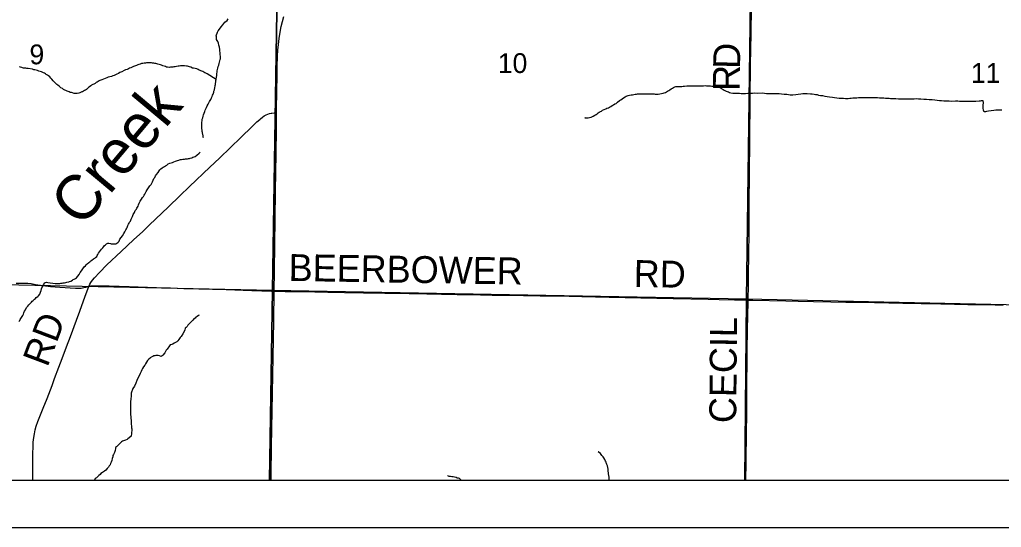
# Model space of a CAD drawing. Extents: x 0 to 34, y 0 to 22.
# Drawn here: x 3.072 to 5.144, y 14 to 15.073 of the extents above; entities that cross this region are included whole.
import ezdxf

# ---------------------------------------------------------------- set-up
doc = ezdxf.new("R2010")
doc.units = 0
for name, color, linetype in [('GM_X_County_Text', 7, 'Continuous'), ('GM_X_Minor_River', 7, 'Continuous'), ('GM_X_Minor_River_Text', 7, 'Continuous'), ('GM_X_Rail_Line_Text', 7, 'Continuous'), ('GM_X_Section', 7, 'Continuous'), ('GM_X_Section_Text', 7, 'Continuous'), ('GM_X_State_Route', 7, 'Continuous'), ('GM_X_Township_Road', 7, 'Continuous'), ('GM_X_Township_Road_Text', 7, 'Continuous'), ('SH_Cut_Line', 7, 'Continuous'), ('SH_Data', 7, 'Continuous')]:
    doc.layers.add(name, color=color, linetype=linetype)

msp = doc.modelspace()

# ---------------------------------------------------------------- linework, layer by layer
at = {"layer": 'GM_X_County_Text'}
msp.add_lwpolyline([(2.1, 14.1), (6.615, 14.1)], dxfattribs=at)
at = {"layer": 'GM_X_Minor_River'}
for points in [[(3.4599, 14.8236), (3.4596, 14.824), (3.4592, 14.8274), (3.4585, 14.8305), (3.4581, 14.8324), (3.4578, 14.8343), (3.4574, 14.8366), (3.457, 14.8396), (3.4567, 14.843), (3.4564, 14.8469), (3.4564, 14.8499), (3.4564, 14.8526), (3.4568, 14.856), (3.4572, 14.859), (3.4576, 14.8624), (3.4584, 14.8655), (3.4592, 14.8685), (3.46, 14.8719), (3.4616, 14.8753), (3.4631, 14.8787), (3.4639, 14.8814), (3.4651, 14.884), (3.4662, 14.8871), (3.4678, 14.8905), (3.4697, 14.8942), (3.4713, 14.8969), (3.4728, 14.8999), (3.4744, 14.9018), (3.4759, 14.9044), (3.4767, 14.9075), (3.4783, 14.9105), (3.4794, 14.9132), (3.4802, 14.9154), (3.481, 14.9177), (3.4818, 14.9196), (3.4822, 14.9219), (3.483, 14.9245), (3.4833, 14.9264), (3.4837, 14.9283), (3.4849, 14.9336), (3.4853, 14.9359), (3.4857, 14.9382), (3.4862, 14.9416), (3.4862, 14.9443), (3.4866, 14.9462), (3.487, 14.9488), (3.4874, 14.9507), (3.4882, 14.9553), (3.4882, 14.9587), (3.4886, 14.9617), (3.489, 14.9648), (3.4898, 14.9674), (3.4902, 14.9701), (3.491, 14.9735), (3.4922, 14.9769), (3.493, 14.9799), (3.4938, 14.9826), (3.4946, 14.9856), (3.4953, 14.9883), (3.4957, 14.9902), (3.4958, 14.9936), (3.4958, 14.9959), (3.4954, 14.9982), (3.4955, 15.0004), (3.4955, 15.0031), (3.4947, 15.0061), (3.4944, 15.01), (3.4937, 15.0145), (3.4926, 15.0187), (3.4915, 15.0229), (3.49, 15.0264), (3.4889, 15.0286), (3.4878, 15.0309), (3.4874, 15.034), (3.4874, 15.0363), (3.4871, 15.0389), (3.4894, 15.0461), (3.4913, 15.0492), (3.494, 15.0529), (3.4971, 15.0575), (3.501, 15.062), (3.5048, 15.0673), (3.5098, 15.071), (3.5121, 15.0744)], [(3.4866, 14.9462), (3.4677, 14.9585), (3.465, 14.9597), (3.4631, 14.9605), (3.4609, 14.962), (3.459, 14.9632), (3.4567, 14.964), (3.4548, 14.9647), (3.4529, 14.9655), (3.451, 14.9663), (3.4491, 14.9671), (3.4457, 14.9686), (3.4423, 14.9694), (3.4393, 14.9702), (3.4366, 14.9706), (3.4336, 14.9722), (3.4302, 14.973), (3.4283, 14.9738), (3.4264, 14.9742), (3.4245, 14.9746), (3.4203, 14.975), (3.4172, 14.975), (3.415, 14.9751), (3.4115, 14.9751), (3.4089, 14.9747), (3.4066, 14.9744), (3.4032, 14.9737), (3.4005, 14.9733), (3.3978, 14.973), (3.3955, 14.9726), (3.3929, 14.9722), (3.3902, 14.9723), (3.3883, 14.9719), (3.3841, 14.9723), (3.3819, 14.9727), (3.3796, 14.9735), (3.3769, 14.9743), (3.3743, 14.9755), (3.3716, 14.9763), (3.369, 14.9771), (3.3663, 14.9779), (3.3637, 14.9786), (3.3618, 14.9794), (3.3595, 14.9798), (3.3572, 14.9802), (3.3553, 14.9806), (3.3523, 14.981), (3.3504, 14.9814), (3.3485, 14.9815), (3.3466, 14.9815), (3.3439, 14.9815), (3.3416, 14.9812), (3.3397, 14.9812), (3.3374, 14.9808), (3.3351, 14.9805), (3.3321, 14.9801), (3.3294, 14.9798), (3.3264, 14.979), (3.3237, 14.9779), (3.3218, 14.9772), (3.3187, 14.9757), (3.3123, 14.9735), (3.3084, 14.9716), (3.3065, 14.9709), (3.3042, 14.9701), (3.3016, 14.969), (3.2989, 14.9675), (3.2958, 14.9664), (3.2924, 14.965), (3.2874, 14.9627), (3.2836, 14.9609), (3.2806, 14.959), (3.2771, 14.9575), (3.2741, 14.956), (3.2714, 14.9549), (3.2687, 14.9538), (3.2657, 14.9527), (3.2626, 14.952), (3.2592, 14.9512), (3.2558, 14.9501), (3.2527, 14.9483), (3.2489, 14.9468), (3.2458, 14.9457), (3.2435, 14.9449), (3.2416, 14.9442), (3.2397, 14.9435), (3.2359, 14.9408), (3.2336, 14.9397), (3.2313, 14.9382), (3.2286, 14.9367), (3.2267, 14.9356), (3.224, 14.9341), (3.2221, 14.9326), (3.2194, 14.9311), (3.2171, 14.9292), (3.2152, 14.9274), (3.2129, 14.9255), (3.211, 14.924), (3.2091, 14.9229), (3.2068, 14.9214), (3.2049, 14.9206)], [(3.2049, 14.9206), (3.203, 14.9199), (3.1988, 14.9184), (3.1969, 14.9177), (3.1938, 14.9169), (3.1908, 14.9166), (3.1874, 14.917), (3.1836, 14.9178), (3.1813, 14.9186), (3.1786, 14.919), (3.1767, 14.9202), (3.1726, 14.9217), (3.1699, 14.9229), (3.1673, 14.9241), (3.1646, 14.9252), (3.1624, 14.9272), (3.1593, 14.9287), (3.1574, 14.9303), (3.1556, 14.9322), (3.1529, 14.9341), (3.1506, 14.936), (3.1488, 14.9376), (3.1457, 14.9406), (3.1431, 14.9433), (3.1401, 14.9468), (3.1382, 14.9491), (3.1356, 14.9522), (3.1333, 14.9541), (3.1311, 14.9556), (3.1284, 14.9572), (3.1265, 14.9583), (3.1242, 14.9599), (3.1224, 14.9607), (3.1182, 14.9622), (3.1155, 14.9634), (3.1125, 14.9642), (3.1098, 14.965), (3.1068, 14.9658), (3.1042, 14.9666), (3.1023, 14.967), (3.0992, 14.9681), (3.0901, 14.9694), (3.0874, 14.9698), (3.0852, 14.9702), (3.0825, 14.9706), (3.0802, 14.9706), (3.0783, 14.971), (3.0764, 14.9714), (3.0738, 14.9726), (3.0715, 14.9734)], [(4.2647, 14.8655), (4.2654, 14.8655), (4.2647, 14.8655), (4.2685, 14.8654), (4.2719, 14.8653), (4.2749, 14.8657), (4.2783, 14.8667), (4.2807, 14.8678), (4.2826, 14.8685), (4.286, 14.8711), (4.2884, 14.8726), (4.2907, 14.874), (4.293, 14.8759), (4.2953, 14.877), (4.2976, 14.8784), (4.2999, 14.8795), (4.3022, 14.8814), (4.3057, 14.8828), (4.3088, 14.8842), (4.3114, 14.8857), (4.3145, 14.8864), (4.3172, 14.8878), (4.3199, 14.8893), (4.3226, 14.8911), (4.3253, 14.893), (4.3284, 14.8948), (4.3307, 14.8959), (4.3338, 14.8981), (4.338, 14.9022), (4.3407, 14.9036), (4.3434, 14.9058), (4.3465, 14.9077), (4.3496, 14.9095), (4.3523, 14.911), (4.3542, 14.9117), (4.3565, 14.9124), (4.3588, 14.9131), (4.3626, 14.9138), (4.3653, 14.9141), (4.3683, 14.9148), (4.371, 14.9151), (4.3736, 14.9154), (4.3759, 14.9157), (4.3786, 14.916), (4.3812, 14.916), (4.3835, 14.9163), (4.3858, 14.9162), (4.3881, 14.9162), (4.3904, 14.9161), (4.3926, 14.9161), (4.3949, 14.916), (4.398, 14.916), (4.401, 14.9159), (4.4044, 14.9158), (4.4074, 14.9157), (4.4109, 14.9157), (4.4131, 14.9156), (4.415, 14.9156), (4.4173, 14.9151), (4.4196, 14.9154), (4.4234, 14.9157), (4.4264, 14.9164), (4.4299, 14.9171), (4.4325, 14.9178), (4.4348, 14.9189), (4.4372, 14.92), (4.4395, 14.9214), (4.4422, 14.9233), (4.4445, 14.9247), (4.4472, 14.9266), (4.4495, 14.928), (4.4518, 14.9291), (4.4549, 14.9306), (4.4568, 14.9313), (4.4587, 14.9316), (4.4621, 14.9315), (4.4693, 14.9318), (4.4724, 14.9321), (4.4754, 14.9324), (4.48, 14.9326), (4.4841, 14.9329), (4.4879, 14.9328), (4.4917, 14.9331), (4.4955, 14.933), (4.4993, 14.9329), (4.5028, 14.9332), (4.5058, 14.9332), (4.5088, 14.9331), (4.5119, 14.933), (4.5149, 14.933), (4.5187, 14.9333), (4.5217, 14.9332), (4.5248, 14.9331), (4.5274, 14.9327), (4.5301, 14.9326), (4.5331, 14.9325), (4.5362, 14.9325), (4.5384, 14.932), (4.5407, 14.932), (4.543, 14.9315), (4.5452, 14.9311)], [(4.5452, 14.9311), (4.5475, 14.9299), (4.5505, 14.9291), (4.5524, 14.9279), (4.5542, 14.9267), (4.5569, 14.9251), (4.5591, 14.9239), (4.5614, 14.9227), (4.5632, 14.9219), (4.5651, 14.9211), (4.5677, 14.9199), (4.5704, 14.9191), (4.573, 14.9183), (4.5768, 14.9174), (4.5802, 14.9174), (4.584, 14.9173), (4.5878, 14.9172), (4.5912, 14.9171), (4.595, 14.917), (4.5988, 14.9169), (4.6037, 14.9168), (4.6087, 14.9171), (4.6136, 14.9173), (4.6186, 14.9172), (4.6231, 14.9179), (4.6284, 14.9177), (4.6402, 14.9178), (4.644, 14.9174), (4.6482, 14.9169), (4.6523, 14.9168), (4.6565, 14.9167), (4.6603, 14.9166), (4.6645, 14.9169), (4.669, 14.9168), (4.6751, 14.9166), (4.68, 14.9161), (4.6853, 14.9156), (4.6914, 14.9151), (4.6978, 14.9142), (4.7039, 14.9141), (4.71, 14.9147), (4.7153, 14.9153), (4.7203, 14.916), (4.7248, 14.9166), (4.729, 14.9169), (4.7343, 14.9168), (4.7412, 14.9162), (4.7449, 14.9158), (4.7487, 14.9153), (4.7518, 14.9148), (4.7548, 14.9144), (4.7582, 14.9135), (4.7623, 14.9127), (4.7665, 14.9122), (4.771, 14.9113), (4.7759, 14.9101), (4.7809, 14.9096), (4.7873, 14.9091), (4.7915, 14.9086), (4.7964, 14.9077), (4.8013, 14.9072), (4.8059, 14.9071), (4.8108, 14.9066), (4.8146, 14.9065), (4.8176, 14.9064), (4.8203, 14.9064), (4.8237, 14.9067), (4.8271, 14.907), (4.8302, 14.9073), (4.8351, 14.9075), (4.8385, 14.9078), (4.8423, 14.9081), (4.8461, 14.908), (4.8499, 14.9083), (4.8533, 14.9083), (4.8568, 14.9082), (4.8674, 14.9083), (4.8716, 14.9082), (4.878, 14.9081), (4.8822, 14.908), (4.8867, 14.9078), (4.8913, 14.9077), (4.8955, 14.9076), (4.8996, 14.9072), (4.9034, 14.9071), (4.9068, 14.9066), (4.9099, 14.9065), (4.9133, 14.9065), (4.9171, 14.9064), (4.9213, 14.9063), (4.9269, 14.9058), (4.9315, 14.9056), (4.936, 14.9055), (4.9414, 14.9054), (4.9463, 14.9053), (4.9512, 14.9056), (4.9554, 14.9055), (4.96, 14.9057), (4.9645, 14.906), (4.9691, 14.9055), (4.9736, 14.9054)], [(4.9736, 14.9054), (4.9804, 14.9049), (4.9858, 14.9048), (4.9918, 14.9042), (4.9979, 14.9037), (5.0036, 14.9032), (5.0085, 14.9027), (5.013, 14.9018), (5.0176, 14.9017), (5.0225, 14.9012), (5.0278, 14.9011), (5.0335, 14.901), (5.0396, 14.9008), (5.0472, 14.901), (5.0517, 14.9009), (5.0555, 14.9008), (5.0593, 14.9007), (5.0635, 14.9006), (5.0669, 14.9006), (5.0696, 14.9005), (5.0726, 14.9004), (5.076, 14.9007), (5.079, 14.9006), (5.0825, 14.9006), (5.0866, 14.9005), (5.0901, 14.9008), (5.0973, 14.901), (5.0999, 14.9013), (5.1022, 14.9016), (5.1049, 14.9016), (5.1055, 14.897), (5.105, 14.8921), (5.1049, 14.8875), (5.1049, 14.8848), (5.1052, 14.8825), (5.1063, 14.8799), (5.1081, 14.8787), (5.1108, 14.8786), (5.1135, 14.8793), (5.1169, 14.88), (5.1226, 14.8806), (5.1276, 14.8813), (5.1321, 14.8819), (5.1359, 14.8822), (5.139, 14.8821), (5.142, 14.8824), (5.145, 14.882)], [(3.3665, 14.7531), (3.368, 14.7554), (3.3703, 14.7573), (3.373, 14.7595), (3.3753, 14.7614), (3.378, 14.7625), (3.3799, 14.764), (3.3826, 14.7655), (3.3856, 14.7678), (3.3891, 14.7692), (3.3921, 14.7703), (3.3944, 14.7711), (3.3975, 14.7722), (3.4009, 14.7737), (3.4032, 14.7744), (3.4055, 14.7751), (3.4078, 14.7759), (3.4097, 14.7766), (3.4116, 14.777), (3.4135, 14.7773), (3.4162, 14.7781), (3.42, 14.778), (3.4219, 14.7784), (3.4238, 14.7784), (3.4264, 14.7787), (3.4283, 14.7791), (3.4302, 14.7794), (3.4321, 14.7798), (3.4352, 14.7805), (3.4379, 14.782), (3.4405, 14.7831), (3.4428, 14.7839), (3.4459, 14.7865), (3.4509, 14.7906), (3.4532, 14.7925), (3.4532, 14.7925)], [(3.1566, 14.5154), (3.1592, 14.5158), (3.1615, 14.5161), (3.1642, 14.5165), (3.1665, 14.5168), (3.1695, 14.5172), (3.1718, 14.5179), (3.1756, 14.519), (3.1775, 14.5198), (3.1802, 14.5205), (3.1833, 14.5224), (3.1852, 14.5235), (3.1875, 14.5246), (3.1898, 14.5261), (3.1924, 14.5276), (3.1978, 14.534), (3.2001, 14.5382), (3.2028, 14.5419), (3.2055, 14.5465), (3.2086, 14.5502), (3.2109, 14.5529), (3.2129, 14.5551), (3.2148, 14.557), (3.2178, 14.5596), (3.2201, 14.5611), (3.2224, 14.563), (3.2247, 14.5645), (3.2282, 14.5671), (3.2305, 14.5686), (3.2324, 14.5701), (3.2347, 14.5724), (3.2355, 14.5743), (3.237, 14.5765), (3.2386, 14.5796), (3.2405, 14.5822), (3.2428, 14.5852), (3.2451, 14.5879), (3.2478, 14.5909), (3.2497, 14.5935), (3.2513, 14.5954), (3.2532, 14.5969), (3.2555, 14.5992), (3.2585, 14.6003), (3.2604, 14.6003), (3.2635, 14.5998), (3.2654, 14.5994), (3.2677, 14.5994), (3.2699, 14.599), (3.2722, 14.599), (3.2749, 14.5993), (3.2768, 14.5997), (3.2802, 14.6027), (3.2818, 14.605), (3.2837, 14.6088), (3.2864, 14.6125), (3.2891, 14.6163), (3.2918, 14.6208), (3.2941, 14.6246), (3.2965, 14.6288), (3.2976, 14.6307), (3.2988, 14.6333), (3.2996, 14.6356), (3.3007, 14.6379), (3.3019, 14.6405), (3.3031, 14.6428), (3.3042, 14.645), (3.3058, 14.6469), (3.3069, 14.6488), (3.3077, 14.6511), (3.3089, 14.6541), (3.3104, 14.6571), (3.312, 14.6613), (3.3143, 14.6655), (3.3162, 14.6692), (3.3186, 14.6723), (3.3197, 14.6742), (3.3209, 14.6764), (3.322, 14.6787), (3.3232, 14.6813), (3.3244, 14.6851), (3.3263, 14.6889), (3.3294, 14.6934), (3.3317, 14.6968), (3.3333, 14.6991), (3.3348, 14.7018), (3.3363, 14.704), (3.3375, 14.7067), (3.3394, 14.7097), (3.3414, 14.7131), (3.3437, 14.7172), (3.3468, 14.7214), (3.3495, 14.7244), (3.3514, 14.7271), (3.3526, 14.7301), (3.3537, 14.7335), (3.3553, 14.7369), (3.3572, 14.7395), (3.3588, 14.7426), (3.3607, 14.7456), (3.3642, 14.7501), (3.3665, 14.7531)], [(3.0706, 14.4353), (3.0722, 14.4372), (3.0733, 14.4395), (3.0745, 14.4414), (3.076, 14.4436), (3.0776, 14.4455), (3.0787, 14.4478), (3.0799, 14.4508), (3.0811, 14.4535), (3.0826, 14.4565), (3.0842, 14.4599), (3.0869, 14.4644), (3.0892, 14.4671), (3.0915, 14.4701), (3.0942, 14.4731), (3.0969, 14.4761), (3.0988, 14.478), (3.1007, 14.4795), (3.1034, 14.4825), (3.1053, 14.4836), (3.1072, 14.4855), (3.1103, 14.4878), (3.1122, 14.4893), (3.1149, 14.493), (3.1157, 14.4949), (3.1161, 14.4972), (3.1173, 14.5002), (3.1181, 14.5037), (3.1192, 14.5063), (3.1208, 14.5097), (3.1227, 14.5124), (3.1235, 14.5146), (3.1246, 14.5165), (3.1285, 14.518), (3.1319, 14.5176), (3.1368, 14.5168), (3.1421, 14.516), (3.1471, 14.5151), (3.1509, 14.5151), (3.1543, 14.5154), (3.1566, 14.5154)], [(3.4506, 14.4486), (3.4492, 14.4477), (3.4465, 14.4454), (3.4442, 14.4443), (3.4427, 14.4424), (3.4407, 14.4413), (3.4377, 14.4379), (3.435, 14.4349), (3.4315, 14.4315), (3.4292, 14.4293), (3.4273, 14.427), (3.4254, 14.4247), (3.4235, 14.4225), (3.4215, 14.4206), (3.4204, 14.4164), (3.4165, 14.4092), (3.413, 14.4032), (3.4111, 14.4013), (3.4095, 14.3994), (3.408, 14.3972), (3.4061, 14.3945), (3.4038, 14.3923), (3.4011, 14.3908), (3.3984, 14.3893), (3.3954, 14.3874), (3.3931, 14.3867), (3.39, 14.3856), (3.3881, 14.3833), (3.3866, 14.3814), (3.3846, 14.3788), (3.3831, 14.3765), (3.3812, 14.3746), (3.3785, 14.369), (3.3746, 14.3641), (3.3727, 14.3625), (3.3704, 14.3614), (3.367, 14.3626), (3.3643, 14.363), (3.362, 14.3634), (3.3594, 14.3631), (3.3571, 14.3627), (3.3552, 14.3624), (3.3529, 14.3612), (3.3498, 14.3594), (3.3479, 14.3583), (3.3449, 14.3556), (3.3418, 14.3526), (3.3395, 14.3488), (3.3375, 14.3454), (3.336, 14.3424), (3.3337, 14.339), (3.3314, 14.336), (3.3298, 14.333), (3.3283, 14.3296), (3.3267, 14.3254), (3.3244, 14.3205), (3.3217, 14.3152), (3.3193, 14.3103), (3.317, 14.3046), (3.3143, 14.2981), (3.3108, 14.2932), (3.3092, 14.2895), (3.3085, 14.2876), (3.3077, 14.2834), (3.3072, 14.2792), (3.3072, 14.2758), (3.3064, 14.2728), (3.3063, 14.264), (3.3063, 14.2575), (3.3062, 14.2541), (3.3058, 14.2515), (3.3062, 14.2484), (3.3062, 14.2458), (3.3061, 14.2408), (3.3068, 14.2317), (3.3071, 14.2252), (3.3075, 14.221), (3.3074, 14.2176), (3.3078, 14.2149), (3.3078, 14.2127), (3.3081, 14.21), (3.3085, 14.2081), (3.3088, 14.2047), (3.3084, 14.2005), (3.3084, 14.1986), (3.3072, 14.1929), (3.3034, 14.1895), (3.3007, 14.1869), (3.2988, 14.1854), (3.2953, 14.1843), (3.2934, 14.1839), (3.2911, 14.1832), (3.2892, 14.1824), (3.2873, 14.1809), (3.2846, 14.1783)], [(3.2846, 14.1783), (3.2823, 14.1757), (3.2792, 14.1727), (3.2766, 14.17), (3.2746, 14.1685), (3.2746, 14.1666), (3.2738, 14.1621), (3.2726, 14.1583), (3.2703, 14.1537), (3.2688, 14.1519), (3.2684, 14.1492), (3.2676, 14.1458), (3.2664, 14.1416), (3.2652, 14.1378), (3.264, 14.1348), (3.2629, 14.1325), (3.2613, 14.1299), (3.2594, 14.1272), (3.2571, 14.1242), (3.2537, 14.1212), (3.251, 14.119), (3.2487, 14.1171), (3.2468, 14.116), (3.2437, 14.1137), (3.2418, 14.1118), (3.2391, 14.1096), (3.2372, 14.1077), (3.2345, 14.1047), (3.2314, 14.1032), (3.2301, 14.1)], [(4.3162, 14.1), (4.3162, 14.1016), (4.3159, 14.1035), (4.3159, 14.1058), (4.315, 14.1134), (4.3146, 14.1157), (4.3143, 14.1176), (4.3144, 14.1195), (4.3141, 14.1233), (4.3134, 14.1268), (4.3123, 14.1298), (4.3113, 14.1329), (4.3102, 14.1352), (4.3095, 14.1375), (4.3084, 14.1398), (4.3077, 14.1417), (4.307, 14.1436), (4.3048, 14.1471), (4.3033, 14.1494), (4.3007, 14.1521), (4.2992, 14.1541), (4.2977, 14.156), (4.2951, 14.1584), (4.2929, 14.1599), (4.2933, 14.1599), (4.2929, 14.1599)], [(3.9747, 14.1097), (3.9751, 14.1097), (3.9777, 14.1085), (3.9811, 14.108), (3.9842, 14.1075), (3.9868, 14.1075), (3.9895, 14.107), (3.9932, 14.1058), (3.9955, 14.105), (3.9974, 14.1046), (3.9993, 14.1038), (4.0015, 14.1022), (4.0036, 14.1)]]:
    msp.add_lwpolyline(points, dxfattribs=at)
at = {"layer": 'GM_X_Rail_Line_Text'}
for points in [[(2.599, 14.1), (3.5997, 14.1), (3.6059, 14.5003), (2.6015, 14.5216)], [(3.5997, 14.1), (4.6027, 14.1), (4.6062, 14.4821), (3.6059, 14.5003)], [(4.6027, 14.1), (5.6017, 14.1), (5.6049, 14.4601), (4.6062, 14.4821)]]:
    msp.add_lwpolyline(points, close=True, dxfattribs=at)
at = {"layer": 'GM_X_Section'}
for points in [[(2.6079, 15.52), (3.6214, 15.4988), (3.6059, 14.5003), (2.6015, 14.5216)], [(3.6214, 15.4988), (4.6192, 15.4834), (4.6062, 14.4821), (3.6059, 14.5003)], [(4.6192, 15.4834), (5.6179, 15.4598), (5.6049, 14.4601), (4.6062, 14.4821)]]:
    msp.add_lwpolyline(points, close=True, dxfattribs=at)
at = {"layer": 'GM_X_State_Route'}
for points in [[(3.6153, 14.9476), (3.6156, 14.9725), (3.6164, 14.9961), (3.6171, 15.0085), (3.6182, 15.0203), (3.6197, 15.0327), (3.6219, 15.0462), (3.6242, 15.0585), (3.6265, 15.0688), (3.6294, 15.0791)], [(3.6026, 14.1), (3.6028, 14.1103), (3.6037, 14.1706), (3.6065, 14.3216), (3.6085, 14.4366), (3.6095, 14.4991), (3.6101, 14.5423), (3.6114, 14.6517), (3.6122, 14.7101), (3.6132, 14.7891), (3.614, 14.8419), (3.6143, 14.8749), (3.6143, 14.8767), (3.615, 14.9277), (3.6153, 14.9476)]]:
    msp.add_lwpolyline(points, dxfattribs=at)
at = {"layer": 'GM_X_Township_Road'}
msp.add_line((3.0997, 14.1), (3.0998, 14.1078), dxfattribs=at)
for points in [[(4.6096, 14.4804), (4.6099, 14.5127), (4.6103, 14.5413), (4.6108, 14.568), (4.6112, 14.5948), (4.6113, 14.6047), (4.6116, 14.6638), (4.6119, 14.6961), (4.612, 14.734), (4.6125, 14.7645), (4.6127, 14.8005), (4.6132, 14.8453), (4.6135, 14.8782), (4.6134, 14.8794), (4.6134, 14.8807), (4.614, 14.9323), (4.6143, 14.9528), (4.6146, 14.982), (4.6149, 15.005), (4.6155, 15.0492), (4.6162, 15.0933)], [(3.5789, 14.8619), (3.5804, 14.8633), (3.5843, 14.8665), (3.5883, 14.8695), (3.5921, 14.8718), (3.5956, 14.8734), (3.5992, 14.8746), (3.603, 14.8754), (3.6042, 14.8755), (3.6143, 14.8767)], [(3.2183, 14.5093), (3.2203, 14.5138), (3.2225, 14.5177), (3.2258, 14.5223), (3.2302, 14.5276), (3.2405, 14.5384), (3.2563, 14.5544), (3.286, 14.5827), (3.3124, 14.6073), (3.332, 14.6254), (3.3455, 14.6382), (3.3864, 14.6774), (3.41, 14.7004), (3.4307, 14.7201), (3.4735, 14.7609), (3.4936, 14.7803), (3.5168, 14.8028), (3.5387, 14.824), (3.563, 14.8472), (3.5729, 14.8566), (3.5789, 14.8619)], [(3.0651, 14.5161), (3.0787, 14.5162), (3.0893, 14.5158), (3.0967, 14.5151), (3.1059, 14.5135), (3.1369, 14.5093), (3.157, 14.5073), (3.1898, 14.5053), (3.1967, 14.5054), (3.2022, 14.5057), (3.2078, 14.5066), (3.2116, 14.5076), (3.2162, 14.5088), (3.2183, 14.5093)], [(3.0998, 14.1078), (3.1, 14.1474), (3.1001, 14.1567), (3.1003, 14.1698), (3.1009, 14.1804), (3.1018, 14.1897), (3.1031, 14.1977), (3.1049, 14.2063), (3.1072, 14.2141), (3.1104, 14.2236), (3.1144, 14.2341), (3.1218, 14.2519), (3.1301, 14.272), (3.1407, 14.2998), (3.1459, 14.3145), (3.1546, 14.3384), (3.1617, 14.3571), (3.171, 14.3814), (3.1791, 14.403), (3.192, 14.438), (3.1989, 14.4566), (3.2107, 14.4887), (3.2183, 14.5093)], [(3.2183, 14.5093), (3.22, 14.5097), (3.2226, 14.5101), (3.2253, 14.5102), (3.2421, 14.5103), (3.2608, 14.5101), (3.303, 14.5091), (3.3608, 14.507), (3.3906, 14.5058), (3.4186, 14.5049), (3.4503, 14.504), (3.5081, 14.5024), (3.5621, 14.5006), (3.6038, 14.4992), (3.6095, 14.4991)], [(3.6095, 14.4991), (3.6324, 14.4987), (3.6628, 14.4982), (3.6951, 14.4975), (3.7225, 14.497), (3.7579, 14.4962), (3.7977, 14.4957), (3.8431, 14.4948), (3.8941, 14.4939), (3.9314, 14.4932), (3.9624, 14.4925), (3.9954, 14.4922), (4.0196, 14.4917), (4.0694, 14.4907), (4.1353, 14.4897), (4.1707, 14.4892), (4.2316, 14.4882), (4.2583, 14.4877), (4.3161, 14.4866), (4.3833, 14.4851), (4.4168, 14.4843), (4.451, 14.4836), (4.525, 14.4824), (4.548, 14.4818), (4.5809, 14.4809), (4.6064, 14.4805), (4.6096, 14.4804)], [(4.6047, 14.1), (4.6052, 14.1366), (4.6059, 14.2038), (4.6064, 14.2349), (4.6067, 14.2771), (4.607, 14.3151), (4.6071, 14.3399), (4.6072, 14.3555), (4.6077, 14.3791), (4.6084, 14.412), (4.6091, 14.4524), (4.6094, 14.4717), (4.6096, 14.4804)], [(4.6096, 14.4804), (4.6195, 14.4803), (4.6891, 14.4788), (4.7152, 14.4783), (4.7475, 14.4775), (4.7842, 14.4768), (4.8159, 14.4761), (4.842, 14.4757), (4.8762, 14.4751), (4.9358, 14.4739), (4.9744, 14.4729), (5.016, 14.4722), (5.0732, 14.4711), (5.1099, 14.4706), (5.1304, 14.47), (5.1478, 14.4694)]]:
    msp.add_lwpolyline(points, dxfattribs=at)
at = {"layer": 'SH_Cut_Line'}
msp.add_lwpolyline([(2.1, 16.5239), (2.1, 14.1), (8.9, 14.1), (8.9, 16.3981)], dxfattribs=at)
at = {"layer": 'SH_Data'}
for p, q in [((2.1, 14.1), (8.9, 14.1)), ((2, 14), (9, 14))]:
    msp.add_line(p, q, dxfattribs=at)

# ---------------------------------------------------------------- texts
at = {"layer": 'GM_X_Minor_River_Text'}
msp.add_text('Creek', height=0.09477, rotation=50.0579, dxfattribs=at).set_placement((3.2027, 14.6308))
at = {"layer": 'GM_X_Section_Text'}
for s, height, p in [('9', 0.0419, (3.0928, 14.9784)), ('10', 0.04186, (4.0812, 14.96)), ('11', 0.04186, (5.0795, 14.9392))]:
    msp.add_text(s, height=height, rotation=0, dxfattribs=at).set_placement(p)
at = {"layer": 'GM_X_Township_Road_Text'}
for s, height, rotation, p in [('D', 0.0568, 88.6885, (4.5922, 14.9683)), ('R', 0.0568, 89.4155, (4.5917, 14.9219)), ('BEERBOWER', 0.05682, 359.1128, (3.6394, 14.5207)), ('RD', 0.05682, 359.0264, (4.3676, 14.5081)), ('RD', 0.05682, 69.3811, (3.1306, 14.3368)), ('CECIL', 0.05682, 89.5299, (4.5842, 14.2202))]:
    msp.add_text(s, height=height, rotation=rotation, dxfattribs=at).set_placement(p)

doc.saveas('drawing.dxf')
